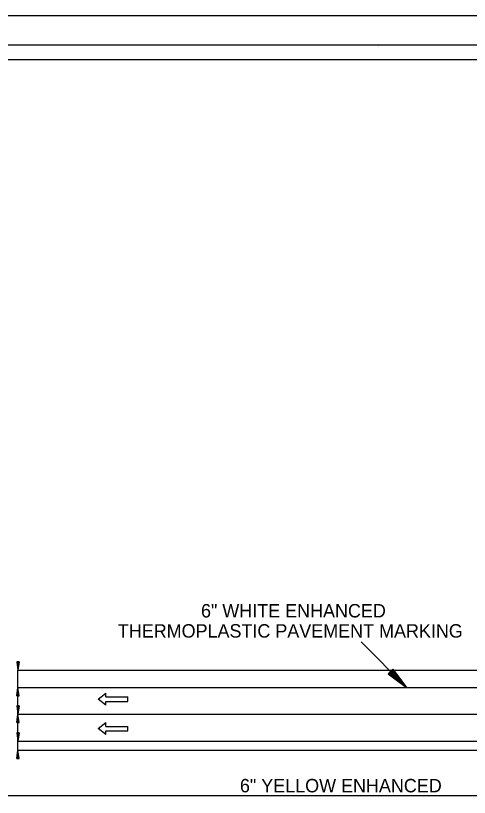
# Model space of a CAD drawing. Extents: x 1369895 to 1370228, y 380116 to 380329.
# Drawn here: x 1370011 to 1370071.8, y 380224.4 to 380329.2 of the extents above; entities that cross this region are included whole.
import ezdxf

# ---------------------------------------------------------------- set-up
doc = ezdxf.new("R2010")
doc.units = 0
for name, color, linetype in [('Default', 7, 'Continuous'), ('R_Border', 7, 'Continuous'), ('R_Horz Alg', 7, 'Continuous'), ('R_MOT', 7, 'Continuous'), ('R_No Plot', 7, 'Continuous'), ('R_Proposed Road', 7, 'Continuous')]:
    doc.layers.add(name, color=color, linetype=linetype)

# ---------------------------------------------------------------- blocks, each defined once
blk = doc.blocks.new('SARROW')
at = {"layer": 'Default'}
for p, q in [((15.6, 3.2), (-13.8, 3.2)), ((-13.8, 3.2), (-13.8, -2.8)), ((15.6, 8.2), (15.6, 3.2)), ((15.6, 8.2), (26, 0.2)), ((26, 0.2), (15.6, -7.8)), ((15.6, -2.8), (-13.8, -2.8)), ((15.6, -2.8), (15.6, -7.8))]:
    blk.add_line(p, q, dxfattribs=at)

msp = doc.modelspace()

# ---------------------------------------------------------------- linework, layer by layer
at = {"layer": 'Default'}
for p, q in [((1370011.1, 380242.62), (1370011.27, 380241.5)), ((1370011.44, 380242.62), (1370011.1, 380242.62)), ((1370011.13, 380242.62), (1370011.27, 380241.69)), ((1370011.16, 380242.62), (1370011.27, 380241.88)), ((1370011.19, 380242.62), (1370011.27, 380242.07)), ((1370011.21, 380242.62), (1370011.27, 380242.26)), ((1370011.24, 380242.62), (1370011.27, 380242.45)), ((1370011.44, 380242.62), (1370011.27, 380241.5)), ((1370011.33, 380242.62), (1370011.27, 380242.26)), ((1370011.38, 380242.62), (1370011.27, 380241.88)), ((1370011.41, 380242.62), (1370011.27, 380241.69)), ((1370011.35, 380242.62), (1370011.27, 380242.07)), ((1370011.3, 380242.62), (1370011.27, 380242.45)), ((1370061.57, 380241.61), (1370060.94, 380240.98)), ((1370061.57, 380241.61), (1370060.94, 380240.98)), ((1370061.57, 380241.61), (1370060.94, 380240.98)), ((1370061.57, 380241.61), (1370063.37, 380239.17)), ((1370061.57, 380241.61), (1370063.37, 380239.17)), ((1370061.57, 380241.61), (1370063.37, 380239.17)), ((1370060.94, 380240.98), (1370063.37, 380239.17)), ((1370060.94, 380240.98), (1370063.37, 380239.17)), ((1370060.94, 380240.98), (1370063.37, 380239.17)), ((1370060.99, 380241.03), (1370063.02, 380239.53)), ((1370060.99, 380241.03), (1370063.02, 380239.53)), ((1370060.99, 380241.03), (1370063.02, 380239.53)), ((1370061.04, 380241.08), (1370062.65, 380239.9)), ((1370061.04, 380241.08), (1370062.65, 380239.9)), ((1370061.04, 380241.08), (1370062.65, 380239.9)), ((1370061.1, 380241.14), (1370062.3, 380240.25)), ((1370061.1, 380241.14), (1370062.3, 380240.25)), ((1370061.1, 380241.14), (1370062.3, 380240.25)), ((1370061.15, 380241.19), (1370061.94, 380240.61)), ((1370061.15, 380241.19), (1370061.94, 380240.61)), ((1370061.15, 380241.19), (1370061.94, 380240.61)), ((1370061.2, 380241.25), (1370061.58, 380240.96)), ((1370061.2, 380241.25), (1370061.58, 380240.96)), ((1370061.2, 380241.25), (1370061.58, 380240.96)), ((1370061.3, 380241.34), (1370061.58, 380240.96)), ((1370061.3, 380241.34), (1370061.58, 380240.96)), ((1370061.3, 380241.34), (1370061.58, 380240.96)), ((1370061.36, 380241.4), (1370061.94, 380240.61)), ((1370061.36, 380241.4), (1370061.94, 380240.61)), ((1370061.36, 380241.4), (1370061.94, 380240.61)), ((1370061.41, 380241.45), (1370062.3, 380240.25)), ((1370061.41, 380241.45), (1370062.3, 380240.25)), ((1370061.41, 380241.45), (1370062.3, 380240.25)), ((1370061.47, 380241.51), (1370062.65, 380239.9)), ((1370061.47, 380241.51), (1370062.65, 380239.9)), ((1370061.47, 380241.51), (1370062.65, 380239.9)), ((1370061.51, 380241.56), (1370063.02, 380239.53)), ((1370061.51, 380241.56), (1370063.02, 380239.53)), ((1370061.51, 380241.56), (1370063.02, 380239.53)), ((1370011.1, 380238.05), (1370011.27, 380239.17)), ((1370011.1, 380238.05), (1370011.27, 380239.17)), ((1370011.1, 380238.05), (1370011.27, 380239.17)), ((1370011.13, 380238.05), (1370011.27, 380238.99)), ((1370011.13, 380238.05), (1370011.27, 380238.99)), ((1370011.13, 380238.05), (1370011.27, 380238.99)), ((1370011.16, 380238.05), (1370011.27, 380238.79)), ((1370011.16, 380238.05), (1370011.27, 380238.79)), ((1370011.16, 380238.05), (1370011.27, 380238.79)), ((1370011.19, 380238.05), (1370011.27, 380238.6)), ((1370011.19, 380238.05), (1370011.27, 380238.6)), ((1370011.19, 380238.05), (1370011.27, 380238.6)), ((1370011.44, 380238.05), (1370011.27, 380239.17)), ((1370011.44, 380238.05), (1370011.27, 380239.17)), ((1370011.44, 380238.05), (1370011.27, 380239.17)), ((1370011.41, 380238.05), (1370011.27, 380238.99)), ((1370011.41, 380238.05), (1370011.27, 380238.99)), ((1370011.41, 380238.05), (1370011.27, 380238.99)), ((1370011.38, 380238.05), (1370011.27, 380238.79)), ((1370011.38, 380238.05), (1370011.27, 380238.79)), ((1370011.38, 380238.05), (1370011.27, 380238.79)), ((1370011.35, 380238.05), (1370011.27, 380238.6)), ((1370011.35, 380238.05), (1370011.27, 380238.6)), ((1370011.35, 380238.05), (1370011.27, 380238.6)), ((1370011.1, 380238.05), (1370011.44, 380238.05)), ((1370011.1, 380238.05), (1370011.44, 380238.05)), ((1370011.1, 380238.05), (1370011.44, 380238.05)), ((1370011.21, 380238.05), (1370011.27, 380238.41)), ((1370011.21, 380238.05), (1370011.27, 380238.41)), ((1370011.21, 380238.05), (1370011.27, 380238.41)), ((1370011.24, 380238.05), (1370011.27, 380238.22)), ((1370011.24, 380238.05), (1370011.27, 380238.22)), ((1370011.24, 380238.05), (1370011.27, 380238.22)), ((1370011.33, 380238.05), (1370011.27, 380238.41)), ((1370011.33, 380238.05), (1370011.27, 380238.41)), ((1370011.33, 380238.05), (1370011.27, 380238.41)), ((1370011.3, 380238.05), (1370011.27, 380238.22)), ((1370011.3, 380238.05), (1370011.27, 380238.22)), ((1370011.3, 380238.05), (1370011.27, 380238.22)), ((1370011.1, 380236.7), (1370011.27, 380235.57)), ((1370011.44, 380236.7), (1370011.1, 380236.7)), ((1370011.1, 380236.7), (1370011.27, 380235.57)), ((1370011.44, 380236.7), (1370011.1, 380236.7)), ((1370011.1, 380236.7), (1370011.27, 380235.57)), ((1370011.44, 380236.7), (1370011.1, 380236.7)), ((1370011.13, 380236.7), (1370011.27, 380235.76)), ((1370011.13, 380236.7), (1370011.27, 380235.76)), ((1370011.13, 380236.7), (1370011.27, 380235.76)), ((1370011.16, 380236.7), (1370011.27, 380235.96)), ((1370011.16, 380236.7), (1370011.27, 380235.96)), ((1370011.16, 380236.7), (1370011.27, 380235.96)), ((1370011.19, 380236.7), (1370011.27, 380236.14)), ((1370011.19, 380236.7), (1370011.27, 380236.14)), ((1370011.19, 380236.7), (1370011.27, 380236.14)), ((1370011.21, 380236.7), (1370011.27, 380236.34)), ((1370011.21, 380236.7), (1370011.27, 380236.34)), ((1370011.21, 380236.7), (1370011.27, 380236.34)), ((1370011.24, 380236.7), (1370011.27, 380236.52)), ((1370011.24, 380236.7), (1370011.27, 380236.52)), ((1370011.24, 380236.7), (1370011.27, 380236.52)), ((1370011.44, 380236.7), (1370011.27, 380235.57)), ((1370011.33, 380236.7), (1370011.27, 380236.34)), ((1370011.38, 380236.7), (1370011.27, 380235.96)), ((1370011.41, 380236.7), (1370011.27, 380235.76)), ((1370011.35, 380236.7), (1370011.27, 380236.14)), ((1370011.3, 380236.7), (1370011.27, 380236.52)), ((1370011.44, 380236.7), (1370011.27, 380235.57)), ((1370011.33, 380236.7), (1370011.27, 380236.34)), ((1370011.38, 380236.7), (1370011.27, 380235.96)), ((1370011.41, 380236.7), (1370011.27, 380235.76)), ((1370011.35, 380236.7), (1370011.27, 380236.14)), ((1370011.3, 380236.7), (1370011.27, 380236.52)), ((1370011.44, 380236.7), (1370011.27, 380235.57)), ((1370011.33, 380236.7), (1370011.27, 380236.34)), ((1370011.38, 380236.7), (1370011.27, 380235.96)), ((1370011.41, 380236.7), (1370011.27, 380235.76)), ((1370011.35, 380236.7), (1370011.27, 380236.14)), ((1370011.3, 380236.7), (1370011.27, 380236.52)), ((1370011.1, 380234.45), (1370011.27, 380235.57)), ((1370011.1, 380234.45), (1370011.27, 380235.57)), ((1370011.1, 380234.45), (1370011.27, 380235.57)), ((1370011.13, 380234.45), (1370011.27, 380235.39)), ((1370011.13, 380234.45), (1370011.27, 380235.39)), ((1370011.13, 380234.45), (1370011.27, 380235.39)), ((1370011.44, 380234.45), (1370011.27, 380235.57)), ((1370011.44, 380234.45), (1370011.27, 380235.57)), ((1370011.44, 380234.45), (1370011.27, 380235.57)), ((1370011.41, 380234.45), (1370011.27, 380235.39)), ((1370011.41, 380234.45), (1370011.27, 380235.39)), ((1370011.41, 380234.45), (1370011.27, 380235.39)), ((1370011.1, 380234.45), (1370011.44, 380234.45)), ((1370011.1, 380234.45), (1370011.44, 380234.45)), ((1370011.1, 380234.45), (1370011.44, 380234.45)), ((1370011.16, 380234.45), (1370011.27, 380235.19)), ((1370011.16, 380234.45), (1370011.27, 380235.19)), ((1370011.16, 380234.45), (1370011.27, 380235.19)), ((1370011.19, 380234.45), (1370011.27, 380235)), ((1370011.19, 380234.45), (1370011.27, 380235)), ((1370011.19, 380234.45), (1370011.27, 380235)), ((1370011.21, 380234.45), (1370011.27, 380234.81)), ((1370011.21, 380234.45), (1370011.27, 380234.81)), ((1370011.21, 380234.45), (1370011.27, 380234.81)), ((1370011.24, 380234.45), (1370011.27, 380234.62)), ((1370011.24, 380234.45), (1370011.27, 380234.62)), ((1370011.24, 380234.45), (1370011.27, 380234.62)), ((1370011.38, 380234.45), (1370011.27, 380235.19)), ((1370011.38, 380234.45), (1370011.27, 380235.19)), ((1370011.38, 380234.45), (1370011.27, 380235.19)), ((1370011.35, 380234.45), (1370011.27, 380235)), ((1370011.35, 380234.45), (1370011.27, 380235)), ((1370011.35, 380234.45), (1370011.27, 380235)), ((1370011.33, 380234.45), (1370011.27, 380234.81)), ((1370011.33, 380234.45), (1370011.27, 380234.81)), ((1370011.33, 380234.45), (1370011.27, 380234.81)), ((1370011.3, 380234.45), (1370011.27, 380234.62)), ((1370011.3, 380234.45), (1370011.27, 380234.62)), ((1370011.3, 380234.45), (1370011.27, 380234.62)), ((1370011.1, 380233.1), (1370011.27, 380231.97)), ((1370011.44, 380233.1), (1370011.1, 380233.1)), ((1370011.1, 380233.1), (1370011.27, 380231.97)), ((1370011.44, 380233.1), (1370011.1, 380233.1)), ((1370011.1, 380233.1), (1370011.27, 380231.97)), ((1370011.44, 380233.1), (1370011.1, 380233.1)), ((1370011.13, 380233.1), (1370011.27, 380232.16)), ((1370011.13, 380233.1), (1370011.27, 380232.16)), ((1370011.13, 380233.1), (1370011.27, 380232.16)), ((1370011.16, 380233.1), (1370011.27, 380232.36)), ((1370011.16, 380233.1), (1370011.27, 380232.36)), ((1370011.16, 380233.1), (1370011.27, 380232.36)), ((1370011.19, 380233.1), (1370011.27, 380232.54)), ((1370011.19, 380233.1), (1370011.27, 380232.54)), ((1370011.19, 380233.1), (1370011.27, 380232.54)), ((1370011.21, 380233.1), (1370011.27, 380232.74)), ((1370011.21, 380233.1), (1370011.27, 380232.74)), ((1370011.21, 380233.1), (1370011.27, 380232.74)), ((1370011.24, 380233.1), (1370011.27, 380232.92)), ((1370011.24, 380233.1), (1370011.27, 380232.92)), ((1370011.24, 380233.1), (1370011.27, 380232.92)), ((1370011.44, 380233.1), (1370011.27, 380231.97)), ((1370011.33, 380233.1), (1370011.27, 380232.74)), ((1370011.38, 380233.1), (1370011.27, 380232.36)), ((1370011.41, 380233.1), (1370011.27, 380232.16)), ((1370011.35, 380233.1), (1370011.27, 380232.54)), ((1370011.3, 380233.1), (1370011.27, 380232.92)), ((1370011.44, 380233.1), (1370011.27, 380231.97)), ((1370011.33, 380233.1), (1370011.27, 380232.74)), ((1370011.38, 380233.1), (1370011.27, 380232.36)), ((1370011.41, 380233.1), (1370011.27, 380232.16)), ((1370011.35, 380233.1), (1370011.27, 380232.54)), ((1370011.3, 380233.1), (1370011.27, 380232.92)), ((1370011.44, 380233.1), (1370011.27, 380231.97)), ((1370011.33, 380233.1), (1370011.27, 380232.74)), ((1370011.38, 380233.1), (1370011.27, 380232.36)), ((1370011.41, 380233.1), (1370011.27, 380232.16)), ((1370011.35, 380233.1), (1370011.27, 380232.54)), ((1370011.3, 380233.1), (1370011.27, 380232.92)), ((1370011.1, 380229.65), (1370011.27, 380230.77)), ((1370011.13, 380229.65), (1370011.27, 380230.59)), ((1370011.16, 380229.65), (1370011.27, 380230.39)), ((1370011.19, 380229.65), (1370011.27, 380230.2)), ((1370011.44, 380229.65), (1370011.27, 380230.77)), ((1370011.41, 380229.65), (1370011.27, 380230.59)), ((1370011.38, 380229.65), (1370011.27, 380230.39)), ((1370011.35, 380229.65), (1370011.27, 380230.2)), ((1370011.1, 380229.65), (1370011.44, 380229.65)), ((1370011.21, 380229.65), (1370011.27, 380230.01)), ((1370011.24, 380229.65), (1370011.27, 380229.82)), ((1370011.33, 380229.65), (1370011.27, 380230.01)), ((1370011.3, 380229.65), (1370011.27, 380229.82))]:
    msp.add_line(p, q, dxfattribs=at)
at = {"layer": 'R_Border'}
for p, q in [((1369907.12, 380325.35), (1370223.3, 380325.35)), ((1370059.64, 380325.09), (1370059.64, 380325.09)), ((1370059.64, 380325.09), (1370059.64, 380325.09))]:
    msp.add_line(p, q, dxfattribs=at)
at = {"layer": 'R_Horz Alg'}
msp.add_line((1370011.27, 380235.57), (1370116.27, 380235.57), dxfattribs=at)
at = {"layer": 'R_No Plot'}
for points in [[(1369894.71, 380329.25), (1370228.05, 380329.25), (1370228.05, 380115.91), (1369894.71, 380115.91)], [(1370221.3, 380224.62), (1369909.12, 380224.62), (1369909.12, 380323.35), (1370158.66, 380323.35), (1370158.66, 380313.47), (1370176.2, 380313.47), (1370200.3, 380313.47), (1370200.3, 380291.14), (1370221.3, 380291.14)], [(1369909.12, 380323.35), (1370158.66, 380323.35), (1370158.66, 380313.47), (1370176.2, 380313.47), (1370200.3, 380313.47), (1370200.3, 380291.14), (1370221.3, 380291.14), (1370221.3, 380121.89), (1369909.12, 380121.89)]]:
    msp.add_lwpolyline(points, close=True, dxfattribs=at)
at = {"layer": 'R_Proposed Road'}
for p, q in [((1370057.29, 380245.26), (1370063.37, 380239.17)), ((1370057.29, 380245.26), (1370063.37, 380239.17)), ((1370057.29, 380245.26), (1370063.37, 380239.17)), ((1370011.27, 380239.17), (1370011.27, 380241.5)), ((1370011.27, 380241.5), (1370116.27, 380241.5)), ((1370011.27, 380235.57), (1370011.27, 380239.17)), ((1370011.27, 380239.17), (1370116.27, 380239.17)), ((1370011.27, 380235.57), (1370011.27, 380239.17)), ((1370011.27, 380235.57), (1370011.27, 380239.17)), ((1370011.27, 380231.97), (1370011.27, 380235.57)), ((1370011.27, 380231.97), (1370011.27, 380235.57)), ((1370011.27, 380231.97), (1370011.27, 380235.57)), ((1370011.27, 380231.97), (1370116.27, 380231.97)), ((1370011.27, 380230.77), (1370011.27, 380231.97)), ((1370011.27, 380230.77), (1370116.27, 380230.77))]:
    msp.add_line(p, q, dxfattribs=at)

# ---------------------------------------------------------------- block references
at = {"layer": 'R_MOT', "xscale": 0.09999996, "yscale": 0.09999996, "rotation": -179.99999999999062}
for p in [(1370024.63, 380237.62), (1370024.63, 380233.67)]:
    msp.add_blockref('SARROW', p, dxfattribs=at)

# ---------------------------------------------------------------- texts
at = {"layer": 'Default'}
for s, p in [('6" WHITE ENHANCED ', (1370035.82, 380248.55)), ('THERMOPLASTIC PAVEMENT MARKING', (1370024.66, 380245.85)), ('6" YELLOW ENHANCED ', (1370041.04, 380225.1))]:
    msp.add_text(s, height=1.8, dxfattribs=at).set_placement(p)

doc.saveas('drawing.dxf')
